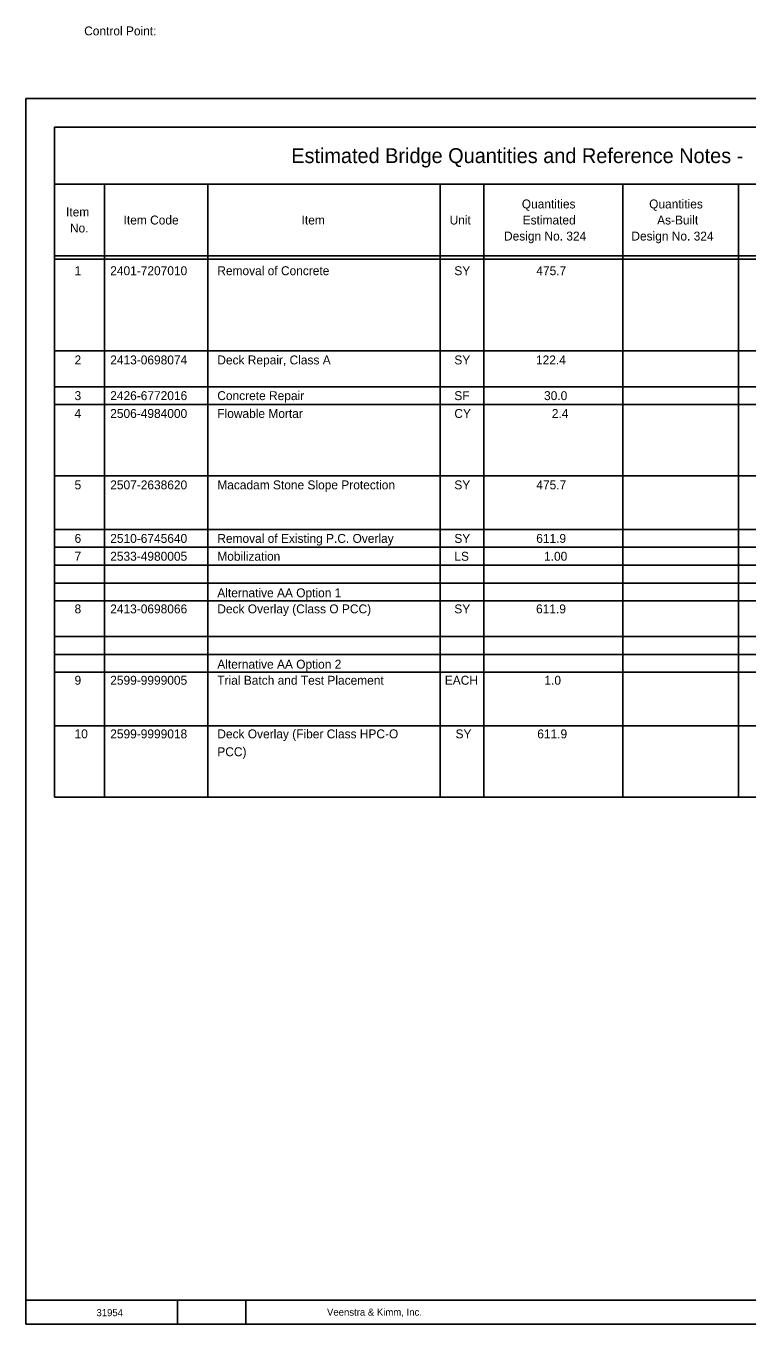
# Model space of a CAD drawing. Extents: x 0.11 to 2.72, y -0.17 to 1.89.
# Drawn here: x 0.11 to 1.121, y 0.07 to 1.888 of the extents above; entities that cross this region are included whole.
import ezdxf

# ---------------------------------------------------------------- set-up
doc = ezdxf.new("R2010")
doc.units = 0
for name, color, linetype in [('SheetBorder', 7, 'Continuous'), ('SheetGridMajor', 7, 'Continuous'), ('SheetGridMinor', 7, 'Continuous'), ('SheetText', 7, 'Continuous')]:
    doc.layers.add(name, color=color, linetype=linetype)

msp = doc.modelspace()

# ---------------------------------------------------------------- linework, layer by layer
at = {"layer": 'SheetBorder'}
for p, q in [((0.1104, 0.1033), (0.3228, 0.1033)), ((0.3228, 0.1033), (0.3228, 0.07)), ((0.3228, 0.1033), (0.4187, 0.1033)), ((0.4187, 0.1033), (0.4187, 0.07)), ((0.4187, 0.1033), (1.8158, 0.1033))]:
    msp.add_line(p, q, dxfattribs=at)
msp.add_lwpolyline([(0.1104, 1.7867), (2.7229, 1.7867), (2.7229, 0.07), (0.1104, 0.07)], close=True, dxfattribs=at)
at = {"layer": 'SheetGridMajor'}
for p, q in [((0.1504, 1.7467), (1.9492, 1.7467)), ((0.1504, 0.808), (0.1504, 1.7467)), ((0.1504, 1.6665), (1.9492, 1.6665)), ((0.2206, 1.6665), (0.2206, 0.808)), ((0.3652, 1.6665), (0.3652, 0.808)), ((0.6908, 1.6665), (0.6908, 0.808)), ((0.752, 1.6665), (0.752, 0.808)), ((0.9467, 1.6665), (0.9467, 0.808)), ((1.1088, 1.6665), (1.1088, 0.808)), ((1.9493, 0.808), (0.1505, 0.808))]:
    msp.add_line(p, q, dxfattribs=at)
at = {"layer": 'SheetGridMinor'}
for p, q in [((0.1504, 1.5664), (1.9492, 1.5664)), ((0.1504, 1.5614), (1.9492, 1.5614)), ((0.1503, 1.433), (1.9491, 1.433)), ((0.1503, 1.383), (1.9491, 1.383)), ((0.1503, 1.358), (1.9491, 1.358)), ((0.1505, 1.258), (1.9493, 1.258)), ((0.1503, 1.183), (1.9491, 1.183)), ((0.1503, 1.158), (1.9491, 1.158)), ((0.1503, 1.133), (1.9491, 1.133)), ((0.1503, 1.108), (1.9491, 1.108)), ((0.1503, 1.083), (1.9491, 1.083)), ((0.1503, 1.033), (1.9491, 1.033)), ((0.1503, 1.008), (1.9491, 1.008)), ((0.1503, 0.983), (1.9491, 0.983)), ((0.1503, 0.908), (1.9491, 0.908))]:
    msp.add_line(p, q, dxfattribs=at)

# ---------------------------------------------------------------- texts
at = {"layer": 'SheetText'}
for s, height, p in [('Control Point:', 0.0125, (0.192, 1.8751)), ('Estimated Bridge Quantities and Reference Notes - ', 0.020833, (0.4821, 1.6962)), ('Quantities', 0.0125, (0.8051, 1.6327)), ('Quantities', 0.0125, (0.9835, 1.6327)), ('Item', 0.0125, (0.1666, 1.6215)), ('Item Code', 0.0125, (0.2472, 1.6102)), ('Item', 0.0125, (0.4966, 1.6102)), ('Unit', 0.0125, (0.704, 1.6102)), ('Estimated', 0.0125, (0.8063, 1.6102)), ('As-Built', 0.0125, (0.9947, 1.6102)), ('No.', 0.0125, (0.172, 1.599)), ('Design No. 324', 0.0125, (0.7802, 1.5877)), ('Design No. 324', 0.0125, (0.9586, 1.5877)), ('1', 0.0125, (0.1785, 1.5392)), ('2401-7207010', 0.0125, (0.2285, 1.5392)), ('Removal of Concrete', 0.0125, (0.3785, 1.5392)), ('SY', 0.0125, (0.7106, 1.5392)), ('475.7', 0.0125, (0.8255, 1.5392)), ('2', 0.0125, (0.1785, 1.4142)), ('2413-0698074', 0.0125, (0.2285, 1.4142)), ('Deck Repair, Class A', 0.0125, (0.3785, 1.4142)), ('SY', 0.0125, (0.7106, 1.4142)), ('122.4', 0.0125, (0.825, 1.4142)), ('3', 0.0125, (0.1785, 1.3642)), ('2426-6772016', 0.0125, (0.2285, 1.3642)), ('Concrete Repair', 0.0125, (0.3785, 1.3642)), ('SF', 0.0125, (0.7106, 1.3642)), ('30.0', 0.0125, (0.8363, 1.3642)), ('4', 0.0125, (0.1785, 1.3392)), ('2506-4984000', 0.0125, (0.2285, 1.3392)), ('Flowable Mortar', 0.0125, (0.3785, 1.3392)), ('CY', 0.0125, (0.7106, 1.3392)), ('2.4', 0.0125, (0.8472, 1.3392)), ('5', 0.0125, (0.1785, 1.2392)), ('2507-2638620', 0.0125, (0.2285, 1.2392)), ('Macadam Stone Slope Protection', 0.0125, (0.3785, 1.2392)), ('SY', 0.0125, (0.7106, 1.2392)), ('475.7', 0.0125, (0.8255, 1.2392)), ('6', 0.0125, (0.1785, 1.1642)), ('2510-6745640', 0.0125, (0.2285, 1.1642)), ('Removal of Existing P.C. Overlay', 0.0125, (0.3785, 1.1642)), ('SY', 0.0125, (0.7106, 1.1642)), ('611.9', 0.0125, (0.8253, 1.1642)), ('7', 0.0125, (0.1785, 1.1392)), ('2533-4980005', 0.0125, (0.2285, 1.1392)), ('Mobilization', 0.0125, (0.3785, 1.1392)), ('LS', 0.0125, (0.7106, 1.1392)), ('1.00', 0.0125, (0.8363, 1.1392)), ('Alternative AA Option 1', 0.0125, (0.3785, 1.088)), ('8', 0.0125, (0.1785, 1.0655)), ('2413-0698066', 0.0125, (0.2285, 1.0655)), ('Deck Overlay (Class O PCC)', 0.0125, (0.3785, 1.0655)), ('SY', 0.0125, (0.7106, 1.0655)), ('611.9', 0.0125, (0.8251, 1.0655)), ('Alternative AA Option 2', 0.0125, (0.3785, 0.988)), ('9', 0.0125, (0.1785, 0.9655)), ('2599-9999005', 0.0125, (0.2285, 0.9655)), ('Trial Batch and Test Placement', 0.0125, (0.3785, 0.9655)), ('EACH', 0.0125, (0.6972, 0.9655)), ('1.0', 0.0125, (0.8368, 0.9655)), ('10', 0.0125, (0.1785, 0.8905)), ('2599-9999018', 0.0125, (0.2285, 0.8904)), ('Deck Overlay (Fiber Class HPC-O', 0.0125, (0.3785, 0.8904)), ('SY', 0.0125, (0.7123, 0.8904)), ('611.9', 0.0125, (0.8268, 0.8904)), ('PCC)', 0.0125, (0.3785, 0.8654)), ('31954', 0.01, (0.2092, 0.081)), ('Veenstra & Kimm, Inc.', 0.01, (0.5322, 0.0817))]:
    msp.add_text(s, height=height, dxfattribs=at).set_placement(p)

doc.saveas('drawing.dxf')
